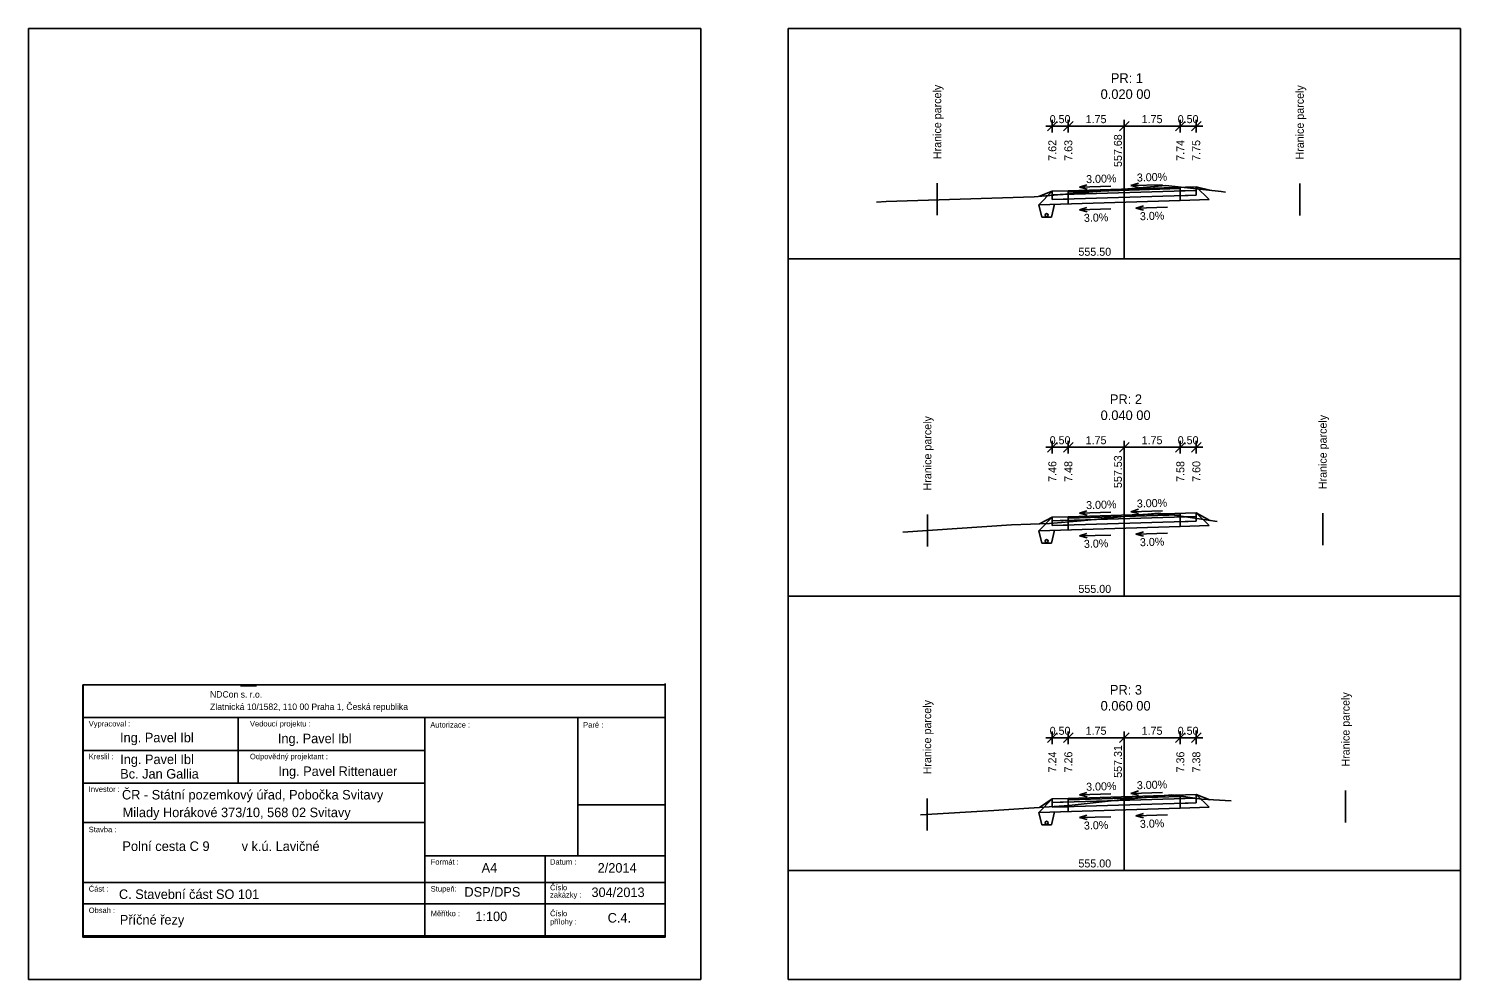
# Model space of a CAD drawing. Extents: x -603737 to -603383, y -1112154 to -1112124.
# Drawn here: x -603736.76 to -603692.02, y -1112153.84 to -1112124.14 of the extents above; entities that cross this region are included whole.
import ezdxf

# ---------------------------------------------------------------- set-up
doc = ezdxf.new("R2010")
doc.units = 0
for name, color, linetype in [('_křivky z hran', 7, 'Continuous'), ('_netisk', 7, 'Continuous'), ('C3D_Podsestava-Popis', 7, 'Continuous'), ('C3D_PP-Popisek', 7, 'Continuous'), ('C3D_PR', 7, 'Continuous'), ('C3D_ZPR', 7, 'Continuous'), ('Default', 7, 'Continuous'), ('konstrukce', 7, 'Continuous'), ('rozpiska', 7, 'Continuous')]:
    doc.layers.add(name, color=color, linetype=linetype)

# ---------------------------------------------------------------- blocks, each defined once
blk = doc.blocks.new('_Oblique')
at = {"layer": 'Default'}
blk.add_line((-0.5, -0.5), (0.5, 0.5), dxfattribs=at)
blk = doc.blocks.new('AeccTickLine')
at = {"layer": 'Default'}
blk.add_line((0, 1), (0, -1), dxfattribs=at)

msp = doc.modelspace()

# ---------------------------------------------------------------- linework, layer by layer
at = {"layer": '_netisk'}
for points in [[(-603736.756, -1112153.84), (-603715.756, -1112153.84), (-603715.756, -1112124.14), (-603736.756, -1112124.14)], [(-603713.023, -1112153.84), (-603692.023, -1112153.84), (-603692.023, -1112124.14), (-603713.023, -1112124.14)]]:
    msp.add_lwpolyline(points, close=True, dxfattribs=at)
at = {"layer": 'C3D_Podsestava-Popis'}
for p, q in [((-603704.973, -1112127.186), (-603702.523, -1112127.186)), ((-603704.773, -1112127.219), (-603704.773, -1112127.336)), ((-603704.273, -1112127.336), (-603704.273, -1112127.204)), ((-603702.523, -1112127.336), (-603702.523, -1112127.152)), ((-603702.523, -1112127.186), (-603700.073, -1112127.186)), ((-603700.773, -1112127.336), (-603700.773, -1112127.099)), ((-603700.273, -1112127.084), (-603700.273, -1112127.336)), ((-603704.973, -1112137.217), (-603702.523, -1112137.217)), ((-603704.773, -1112137.404), (-603704.773, -1112137.367)), ((-603704.273, -1112137.389), (-603704.273, -1112137.367)), ((-603702.523, -1112137.217), (-603700.073, -1112137.217)), ((-603702.523, -1112137.367), (-603702.523, -1112137.336)), ((-603700.773, -1112137.367), (-603700.773, -1112137.284)), ((-603700.273, -1112137.269), (-603700.273, -1112137.367)), ((-603704.973, -1112146.294), (-603702.523, -1112146.294)), ((-603704.773, -1112146.203), (-603704.773, -1112146.444)), ((-603704.273, -1112146.444), (-603704.273, -1112146.188)), ((-603702.523, -1112146.444), (-603702.523, -1112146.135)), ((-603702.523, -1112146.294), (-603700.073, -1112146.294)), ((-603700.773, -1112146.444), (-603700.773, -1112146.083)), ((-603700.273, -1112146.068), (-603700.273, -1112146.444))]:
    msp.add_line(p, q, dxfattribs=at)
at = {"layer": 'C3D_PP-Popisek'}
for p, q in [((-603703.926, -1112129.094), (-603703.689, -1112129.018)), ((-603702.315, -1112129.045), (-603702.078, -1112128.97)), ((-603701.331, -1112129.016), (-603702.315, -1112129.045)), ((-603702.315, -1112129.045), (-603702.074, -1112129.106)), ((-603702.942, -1112129.064), (-603703.926, -1112129.094)), ((-603703.926, -1112129.094), (-603703.685, -1112129.155)), ((-603703.926, -1112129.804), (-603703.689, -1112129.728)), ((-603702.942, -1112129.774), (-603703.926, -1112129.804)), ((-603703.926, -1112129.804), (-603703.685, -1112129.865)), ((-603702.161, -1112129.751), (-603701.925, -1112129.676)), ((-603701.177, -1112129.721), (-603702.161, -1112129.751)), ((-603702.161, -1112129.751), (-603701.92, -1112129.812)), ((-603703.926, -1112139.278), (-603703.689, -1112139.203)), ((-603702.942, -1112139.249), (-603703.926, -1112139.278)), ((-603703.926, -1112139.278), (-603703.685, -1112139.339)), ((-603702.315, -1112139.23), (-603702.078, -1112139.154)), ((-603701.331, -1112139.2), (-603702.315, -1112139.23)), ((-603702.315, -1112139.23), (-603702.074, -1112139.291)), ((-603703.926, -1112139.988), (-603703.689, -1112139.913)), ((-603702.942, -1112139.959), (-603703.926, -1112139.988)), ((-603703.926, -1112139.988), (-603703.685, -1112140.049)), ((-603702.161, -1112139.935), (-603701.925, -1112139.86)), ((-603701.177, -1112139.906), (-603702.161, -1112139.935)), ((-603702.161, -1112139.935), (-603701.92, -1112139.996)), ((-603703.926, -1112148.077), (-603703.689, -1112148.002)), ((-603702.942, -1112148.048), (-603703.926, -1112148.077)), ((-603703.926, -1112148.077), (-603703.685, -1112148.138)), ((-603702.315, -1112148.029), (-603702.078, -1112147.953)), ((-603701.331, -1112147.999), (-603702.315, -1112148.029)), ((-603702.315, -1112148.029), (-603702.074, -1112148.09)), ((-603703.926, -1112148.787), (-603703.689, -1112148.712)), ((-603702.161, -1112148.734), (-603701.925, -1112148.659)), ((-603701.177, -1112148.705), (-603702.161, -1112148.734)), ((-603702.942, -1112148.758), (-603703.926, -1112148.787)), ((-603703.926, -1112148.787), (-603703.685, -1112148.848)), ((-603702.161, -1112148.734), (-603701.92, -1112148.795))]:
    msp.add_line(p, q, dxfattribs=at)
at = {"layer": 'C3D_PR'}
for points in [[(-603710.261, -1112129.563), (-603709.964, -1112129.543), (-603705.34, -1112129.392), (-603702.523, -1112129.154), (-603701.468, -1112129.064), (-603701.226, -1112129.04), (-603699.496, -1112129.224), (-603699.361, -1112129.245)], [(-603709.443, -1112139.868), (-603706.044, -1112139.643), (-603704.86, -1112139.604), (-603703.869, -1112139.52), (-603702.523, -1112139.384), (-603701.462, -1112139.277), (-603701.026, -1112139.324), (-603699.624, -1112139.538)], [(-603708.895, -1112148.699), (-603706.597, -1112148.563), (-603704.247, -1112148.407), (-603702.649, -1112148.234), (-603702.523, -1112148.221), (-603701.034, -1112148.071), (-603700.103, -1112148.213), (-603699.181, -1112148.263)]]:
    msp.add_lwpolyline(points, dxfattribs=at)
at = {"layer": 'C3D_ZPR'}
for p, q in [((-603702.523, -1112131.336), (-603702.523, -1112127.336)), ((-603708.368, -1112129.966), (-603708.368, -1112128.966)), ((-603697.039, -1112129.98), (-603697.039, -1112128.98)), ((-603705.195, -1112129.642), (-603704.773, -1112129.219)), ((-603704.773, -1112129.219), (-603705.168, -1112129.378)), ((-603705.168, -1112129.378), (-603704.773, -1112129.219)), ((-603704.773, -1112129.329), (-603700.273, -1112129.194)), ((-603704.773, -1112129.219), (-603704.273, -1112129.204)), ((-603704.773, -1112129.479), (-603704.773, -1112129.219)), ((-603704.773, -1112129.479), (-603704.773, -1112129.219)), ((-603704.773, -1112129.329), (-603704.273, -1112129.314)), ((-603704.773, -1112129.479), (-603700.273, -1112129.344)), ((-603704.773, -1112129.479), (-603704.273, -1112129.464)), ((-603704.273, -1112129.204), (-603700.273, -1112129.084)), ((-603704.273, -1112129.244), (-603700.773, -1112129.139)), ((-603704.273, -1112129.614), (-603704.273, -1112129.204)), ((-603704.273, -1112129.314), (-603704.273, -1112129.244)), ((-603704.273, -1112129.614), (-603704.273, -1112129.464)), ((-603700.773, -1112129.139), (-603700.773, -1112129.099)), ((-603700.773, -1112129.509), (-603700.773, -1112129.099)), ((-603700.773, -1112129.209), (-603700.273, -1112129.194)), ((-603700.773, -1112129.359), (-603700.773, -1112129.209)), ((-603700.773, -1112129.359), (-603700.273, -1112129.344)), ((-603700.773, -1112129.509), (-603699.875, -1112129.482)), ((-603700.273, -1112129.344), (-603700.273, -1112129.084)), ((-603700.273, -1112129.344), (-603700.273, -1112129.084)), ((-603700.273, -1112129.084), (-603699.875, -1112129.482)), ((-603700.273, -1112129.084), (-603699.848, -1112129.186)), ((-603700.273, -1112129.084), (-603699.848, -1112129.186)), ((-603705.195, -1112129.642), (-603700.773, -1112129.509)), ((-603713.023, -1112131.336), (-603692.023, -1112131.336)), ((-603702.523, -1112141.867), (-603702.523, -1112137.367)), ((-603708.675, -1112140.317), (-603708.675, -1112139.317)), ((-603704.273, -1112139.389), (-603700.273, -1112139.269)), ((-603704.273, -1112139.429), (-603700.773, -1112139.324)), ((-603700.773, -1112139.324), (-603700.773, -1112139.284)), ((-603700.773, -1112139.694), (-603700.773, -1112139.284)), ((-603700.273, -1112139.529), (-603700.273, -1112139.269)), ((-603700.273, -1112139.529), (-603700.273, -1112139.269)), ((-603699.875, -1112139.667), (-603700.273, -1112139.269)), ((-603700.273, -1112139.269), (-603699.848, -1112139.504)), ((-603700.273, -1112139.269), (-603699.848, -1112139.504)), ((-603696.324, -1112140.279), (-603696.324, -1112139.279)), ((-603705.195, -1112139.826), (-603704.773, -1112139.404)), ((-603705.195, -1112139.826), (-603700.773, -1112139.694)), ((-603704.773, -1112139.404), (-603705.168, -1112139.614)), ((-603705.168, -1112139.614), (-603704.773, -1112139.404)), ((-603704.773, -1112139.514), (-603700.273, -1112139.379)), ((-603704.773, -1112139.404), (-603704.273, -1112139.389)), ((-603704.773, -1112139.664), (-603704.773, -1112139.404)), ((-603704.773, -1112139.664), (-603704.773, -1112139.404)), ((-603704.773, -1112139.514), (-603704.273, -1112139.499)), ((-603704.773, -1112139.664), (-603700.273, -1112139.529)), ((-603704.773, -1112139.664), (-603704.273, -1112139.649)), ((-603704.273, -1112139.799), (-603704.273, -1112139.389)), ((-603704.273, -1112139.499), (-603704.273, -1112139.429)), ((-603704.273, -1112139.799), (-603704.273, -1112139.649)), ((-603700.773, -1112139.394), (-603700.273, -1112139.379)), ((-603700.773, -1112139.544), (-603700.773, -1112139.394)), ((-603700.773, -1112139.544), (-603700.273, -1112139.529)), ((-603700.773, -1112139.694), (-603699.875, -1112139.667)), ((-603713.023, -1112141.867), (-603692.023, -1112141.867)), ((-603702.523, -1112150.444), (-603702.523, -1112146.444)), ((-603708.682, -1112149.186), (-603708.682, -1112148.186)), ((-603705.195, -1112148.625), (-603704.773, -1112148.203)), ((-603704.773, -1112148.203), (-603705.168, -1112148.468)), ((-603705.168, -1112148.468), (-603704.773, -1112148.203)), ((-603704.773, -1112148.313), (-603700.273, -1112148.178)), ((-603704.773, -1112148.203), (-603704.273, -1112148.188)), ((-603704.773, -1112148.463), (-603704.773, -1112148.203)), ((-603704.773, -1112148.463), (-603704.773, -1112148.203)), ((-603704.273, -1112148.188), (-603700.273, -1112148.068)), ((-603704.273, -1112148.228), (-603700.773, -1112148.123)), ((-603704.273, -1112148.598), (-603704.273, -1112148.188)), ((-603704.273, -1112148.298), (-603704.273, -1112148.228)), ((-603700.773, -1112148.123), (-603700.773, -1112148.083)), ((-603700.773, -1112148.493), (-603700.773, -1112148.083)), ((-603700.773, -1112148.193), (-603700.273, -1112148.178)), ((-603700.773, -1112148.343), (-603700.773, -1112148.193)), ((-603700.273, -1112148.328), (-603700.273, -1112148.068)), ((-603700.273, -1112148.328), (-603700.273, -1112148.068)), ((-603700.273, -1112148.068), (-603699.875, -1112148.466)), ((-603700.273, -1112148.068), (-603699.848, -1112148.227)), ((-603700.273, -1112148.068), (-603699.848, -1112148.227)), ((-603695.609, -1112148.944), (-603695.609, -1112147.944)), ((-603705.195, -1112148.625), (-603700.773, -1112148.493)), ((-603704.773, -1112148.313), (-603704.273, -1112148.298)), ((-603704.773, -1112148.463), (-603700.273, -1112148.328)), ((-603704.773, -1112148.463), (-603704.273, -1112148.448)), ((-603704.273, -1112148.598), (-603704.273, -1112148.448)), ((-603700.773, -1112148.343), (-603700.273, -1112148.328)), ((-603700.773, -1112148.493), (-603699.875, -1112148.466)), ((-603713.023, -1112150.444), (-603692.023, -1112150.444))]:
    msp.add_line(p, q, dxfattribs=at)
at = {"layer": 'Default'}
msp.add_line((-603730.139, -1112144.667), (-603729.636, -1112144.667), dxfattribs=at)
msp.add_lwpolyline([(-603735.058, -1112144.64), (-603716.871, -1112144.64), (-603716.871, -1112152.523), (-603735.058, -1112152.523)], close=True, dxfattribs=at)
at = {"layer": 'konstrukce'}
for p, q in [((-603705.099, -1112130.027), (-603705.195, -1112129.642)), ((-603704.799, -1112130.027), (-603704.699, -1112129.627)), ((-603704.799, -1112130.027), (-603705.099, -1112130.027)), ((-603705.099, -1112140.211), (-603705.195, -1112139.826)), ((-603704.799, -1112140.211), (-603705.099, -1112140.211)), ((-603704.799, -1112140.211), (-603704.699, -1112139.811)), ((-603705.099, -1112149.01), (-603705.195, -1112148.625)), ((-603704.799, -1112149.01), (-603704.699, -1112148.61)), ((-603704.799, -1112149.01), (-603705.099, -1112149.01))]:
    msp.add_line(p, q, dxfattribs=at)
for centre in [(-603704.949, -1112129.967), (-603704.949, -1112140.151), (-603704.949, -1112148.95)]:
    msp.add_circle(centre, 0.05, dxfattribs=at)
at = {"layer": 'rozpiska'}
for p, q in [((-603716.871, -1112144.64), (-603735.058, -1112144.64)), ((-603716.871, -1112144.6), (-603716.871, -1112152.523)), ((-603716.871, -1112145.663), (-603735.058, -1112145.663)), ((-603730.213, -1112145.663), (-603730.213, -1112147.709)), ((-603724.373, -1112145.663), (-603724.373, -1112152.483)), ((-603719.599, -1112145.663), (-603719.599, -1112149.982)), ((-603724.373, -1112146.686), (-603735.058, -1112146.686)), ((-603724.373, -1112147.709), (-603735.058, -1112147.709)), ((-603716.871, -1112148.391), (-603719.599, -1112148.391)), ((-603724.378, -1112148.944), (-603735.063, -1112148.944)), ((-603716.871, -1112149.982), (-603724.373, -1112149.982)), ((-603720.622, -1112149.982), (-603720.622, -1112152.483)), ((-603735.058, -1112150.819), (-603716.871, -1112150.819)), ((-603735.058, -1112151.481), (-603716.871, -1112151.481)), ((-603716.871, -1112152.483), (-603735.058, -1112152.483))]:
    msp.add_line(p, q, dxfattribs=at)
msp.add_lwpolyline([(-603735.053, -1112144.64), (-603735.053, -1112152.49)], dxfattribs=at)

# ---------------------------------------------------------------- block references
at = {"layer": '_křivky z hran', "rotation": 180}
for name, p, xscale, yscale in [('_Oblique', (-603704.773, -1112127.186), 0.3, 0.3), ('AeccTickLine', (-603704.773, -1112127.186), 0.2, 0.20000000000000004), ('_Oblique', (-603704.273, -1112127.186), 0.3, 0.3), ('AeccTickLine', (-603704.273, -1112127.186), 0.2, 0.20000000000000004), ('_Oblique', (-603702.523, -1112127.186), 0.3, 0.3), ('AeccTickLine', (-603702.523, -1112127.186), 0.2, 0.20000000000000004), ('_Oblique', (-603704.773, -1112137.217), 0.3, 0.3), ('AeccTickLine', (-603704.773, -1112137.217), 0.2, 0.20000000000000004), ('_Oblique', (-603704.273, -1112137.217), 0.3, 0.3), ('AeccTickLine', (-603704.273, -1112137.217), 0.2, 0.20000000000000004), ('_Oblique', (-603702.523, -1112137.217), 0.3, 0.3), ('AeccTickLine', (-603702.523, -1112137.217), 0.2, 0.20000000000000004), ('_Oblique', (-603704.773, -1112146.294), 0.3, 0.3), ('AeccTickLine', (-603704.773, -1112146.294), 0.2, 0.20000000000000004), ('_Oblique', (-603704.273, -1112146.294), 0.3, 0.3), ('AeccTickLine', (-603704.273, -1112146.294), 0.2, 0.20000000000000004), ('_Oblique', (-603702.523, -1112146.294), 0.3, 0.3), ('AeccTickLine', (-603702.523, -1112146.294), 0.2, 0.20000000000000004)]:
    msp.add_blockref(name, p, dxfattribs=dict(at, xscale=xscale, yscale=yscale))
at = {"layer": '_křivky z hran'}
for name, p, xscale, yscale in [('_Oblique', (-603702.523, -1112127.186), 0.3, 0.3), ('AeccTickLine', (-603702.523, -1112127.186), 0.2, 0.20000000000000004), ('_Oblique', (-603700.773, -1112127.186), 0.3, 0.3), ('AeccTickLine', (-603700.773, -1112127.186), 0.2, 0.20000000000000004), ('_Oblique', (-603700.273, -1112127.186), 0.3, 0.3), ('AeccTickLine', (-603700.273, -1112127.186), 0.2, 0.20000000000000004), ('_Oblique', (-603702.523, -1112137.217), 0.3, 0.3), ('AeccTickLine', (-603702.523, -1112137.217), 0.2, 0.20000000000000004), ('_Oblique', (-603700.773, -1112137.217), 0.3, 0.3), ('AeccTickLine', (-603700.773, -1112137.217), 0.2, 0.20000000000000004), ('_Oblique', (-603700.273, -1112137.217), 0.3, 0.3), ('AeccTickLine', (-603700.273, -1112137.217), 0.2, 0.20000000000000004), ('_Oblique', (-603702.523, -1112146.294), 0.3, 0.3), ('AeccTickLine', (-603702.523, -1112146.294), 0.2, 0.20000000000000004), ('_Oblique', (-603700.773, -1112146.294), 0.3, 0.3), ('AeccTickLine', (-603700.773, -1112146.294), 0.2, 0.20000000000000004), ('_Oblique', (-603700.273, -1112146.294), 0.3, 0.3), ('AeccTickLine', (-603700.273, -1112146.294), 0.2, 0.20000000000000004)]:
    msp.add_blockref(name, p, dxfattribs=dict(at, xscale=xscale, yscale=yscale))

# ---------------------------------------------------------------- texts
at = {"layer": 'C3D_Podsestava-Popis'}
for s, rotation, p in [('0.50', 360, (-603704.854, -1112127.092)), ('1.75', 360, (-603703.731, -1112127.092)), ('1.75', 360, (-603703.731, -1112127.092)), ('1.75', 360, (-603701.981, -1112127.092)), ('1.75', 360, (-603701.981, -1112127.092)), ('0.50', 360, (-603700.854, -1112127.092)), ('7.62', 90, (-603704.647, -1112128.267)), ('7.62', 90, (-603704.647, -1112128.267)), ('7.63', 90, (-603704.147, -1112128.268)), ('557.68', 90, (-603702.597, -1112128.463)), ('7.74', 90, (-603700.648, -1112128.268)), ('7.75', 90, (-603700.151, -1112128.269)), ('7.75', 90, (-603700.151, -1112128.269)), ('3.00%', 1.7184, (-603703.712, -1112128.968)), ('3.00%', 1.7184, (-603702.128, -1112128.919)), ('3.0%', 1.7184, (-603703.781, -1112130.179)), ('3.0%', 1.7184, (-603702.031, -1112130.126)), ('0.50', 360, (-603704.854, -1112137.123)), ('1.75', 360, (-603703.731, -1112137.123)), ('1.75', 360, (-603703.731, -1112137.123)), ('1.75', 360, (-603701.981, -1112137.123)), ('1.75', 360, (-603701.981, -1112137.123)), ('0.50', 360, (-603700.854, -1112137.123)), ('557.53', 90, (-603702.597, -1112138.493)), ('7.46', 90, (-603704.647, -1112138.299)), ('7.46', 90, (-603704.647, -1112138.299)), ('7.48', 90, (-603704.147, -1112138.299)), ('7.58', 90, (-603700.647, -1112138.299)), ('7.60', 90, (-603700.147, -1112138.298)), ('7.60', 90, (-603700.147, -1112138.298)), ('3.00%', 1.7184, (-603703.712, -1112139.152)), ('3.00%', 1.7184, (-603702.128, -1112139.103)), ('3.0%', 1.7184, (-603703.781, -1112140.363)), ('3.0%', 1.7184, (-603702.031, -1112140.311)), ('0.50', 360, (-603704.854, -1112146.2)), ('1.75', 360, (-603703.731, -1112146.2)), ('1.75', 360, (-603703.731, -1112146.2)), ('1.75', 360, (-603701.981, -1112146.2)), ('1.75', 360, (-603701.981, -1112146.2)), ('0.50', 360, (-603700.854, -1112146.2)), ('7.24', 90, (-603704.647, -1112147.375)), ('7.24', 90, (-603704.647, -1112147.375)), ('7.26', 90, (-603704.147, -1112147.375)), ('557.31', 90, (-603702.597, -1112147.545)), ('7.36', 90, (-603700.647, -1112147.375)), ('7.38', 90, (-603700.147, -1112147.376)), ('7.38', 90, (-603700.147, -1112147.376)), ('3.00%', 1.7184, (-603703.712, -1112147.951)), ('3.00%', 1.7184, (-603702.128, -1112147.902)), ('3.0%', 1.7184, (-603703.781, -1112149.162)), ('3.0%', 1.7184, (-603702.031, -1112149.11))]:
    msp.add_text(s, height=0.25, rotation=rotation, dxfattribs=at).set_placement(p)
at = {"layer": 'C3D_ZPR'}
for s, rotation, p in [('Hranice parcely', 90, (-603708.243, -1112128.216)), ('Hranice parcely', 90, (-603696.914, -1112128.23)), ('555.50', 360, (-603703.956, -1112131.236)), ('Hranice parcely', 90, (-603708.55, -1112138.567)), ('Hranice parcely', 90, (-603696.199, -1112138.529)), ('555.00', 360, (-603703.956, -1112141.767)), ('Hranice parcely', 90, (-603708.557, -1112147.436)), ('Hranice parcely', 90, (-603695.484, -1112147.194)), ('555.00', 360, (-603703.956, -1112150.344))]:
    msp.add_text(s, height=0.25, rotation=rotation, dxfattribs=at).set_placement(p)
for s, p in [('PR: 1', (-603702.943, -1112125.836)), ('0.020 00', (-603703.263, -1112126.336)), ('PR: 2', (-603702.973, -1112135.867)), ('0.040 00', (-603703.263, -1112136.367)), ('PR: 3', (-603702.973, -1112144.944)), ('0.060 00', (-603703.263, -1112145.444))]:
    msp.add_text(s, height=0.3, dxfattribs=at).set_placement(p)
at = {"layer": 'rozpiska'}
for s, height, p in [('NDCon s. r.o.', 0.20093, (-603731.087, -1112145.038)), ('Zlatnická 10/1582, 110 00 Praha 1, Česká republika', 0.20093, (-603731.087, -1112145.424)), ('Vypracoval :', 0.17051, (-603734.878, -1112145.94)), ('Vedoucí projektu :', 0.17051, (-603729.841, -1112145.94)), ('Autorizace :', 0.17051, (-603724.206, -1112145.974)), ('Paré :', 0.1705, (-603719.431, -1112145.974)), ('Ing. Pavel Ibl', 0.29768, (-603733.9, -1112146.435)), ('Ing. Pavel Ibl', 0.29768, (-603728.969, -1112146.463)), ('Kreslil :', 0.1705, (-603734.878, -1112146.963)), ('Ing. Pavel Ibl', 0.29768, (-603733.895, -1112147.115)), ('Odpovědný projektant :', 0.17051, (-603729.841, -1112146.963)), ('Bc. Jan Gallia', 0.29768, (-603733.895, -1112147.568)), ('Ing. Pavel Rittenauer', 0.29768, (-603728.953, -1112147.486)), ('Investor :', 0.1705, (-603734.878, -1112147.983)), ('ČR - Státní pozemkový úřad, Pobočka Svitavy', 0.29768, (-603733.84, -1112148.221)), ('Milady Horákové 373/10, 568 02 Svitavy', 0.29768, (-603733.819, -1112148.773)), ('Stavba :', 0.1705, (-603734.878, -1112149.243)), ('Polní cesta C 9 ', 0.30069, (-603733.828, -1112149.83)), ('v\xa0k.ú. Lavičné', 0.29768, (-603730.1, -1112149.83)), ('Formát :', 0.1705, (-603724.193, -1112150.256)), (' A4', 0.2977, (-603722.713, -1112150.505)), ('Datum :', 0.1705, (-603720.465, -1112150.256)), ('2/2014', 0.2977, (-603718.977, -1112150.505)), ('Část :', 0.1705, (-603734.878, -1112151.097)), ('Stupeň:', 0.1705, (-603724.193, -1112151.097)), ('DSP/DPS', 0.2977, (-603723.14, -1112151.257)), ('Číslo', 0.1705, (-603720.465, -1112151.056)), ('304/2013', 0.2977, (-603719.171, -1112151.269)), ('C. Stavební část SO 101', 0.29768, (-603733.934, -1112151.329)), ('zakázky :', 0.1705, (-603720.465, -1112151.284)), ('Obsah :', 0.1705, (-603734.878, -1112151.768)), ('Příčné řezy', 0.29768, (-603733.907, -1112152.127)), ('Měřítko :', 0.1705, (-603724.193, -1112151.867)), ('1:100', 0.2977, (-603722.8, -1112152.022)), ('Číslo', 0.1705, (-603720.465, -1112151.867)), ('C.4.', 0.2977, (-603718.665, -1112152.066)), ('přílohy :', 0.1705, (-603720.465, -1112152.126))]:
    msp.add_text(s, height=height, dxfattribs=at).set_placement(p)

doc.saveas('drawing.dxf')
